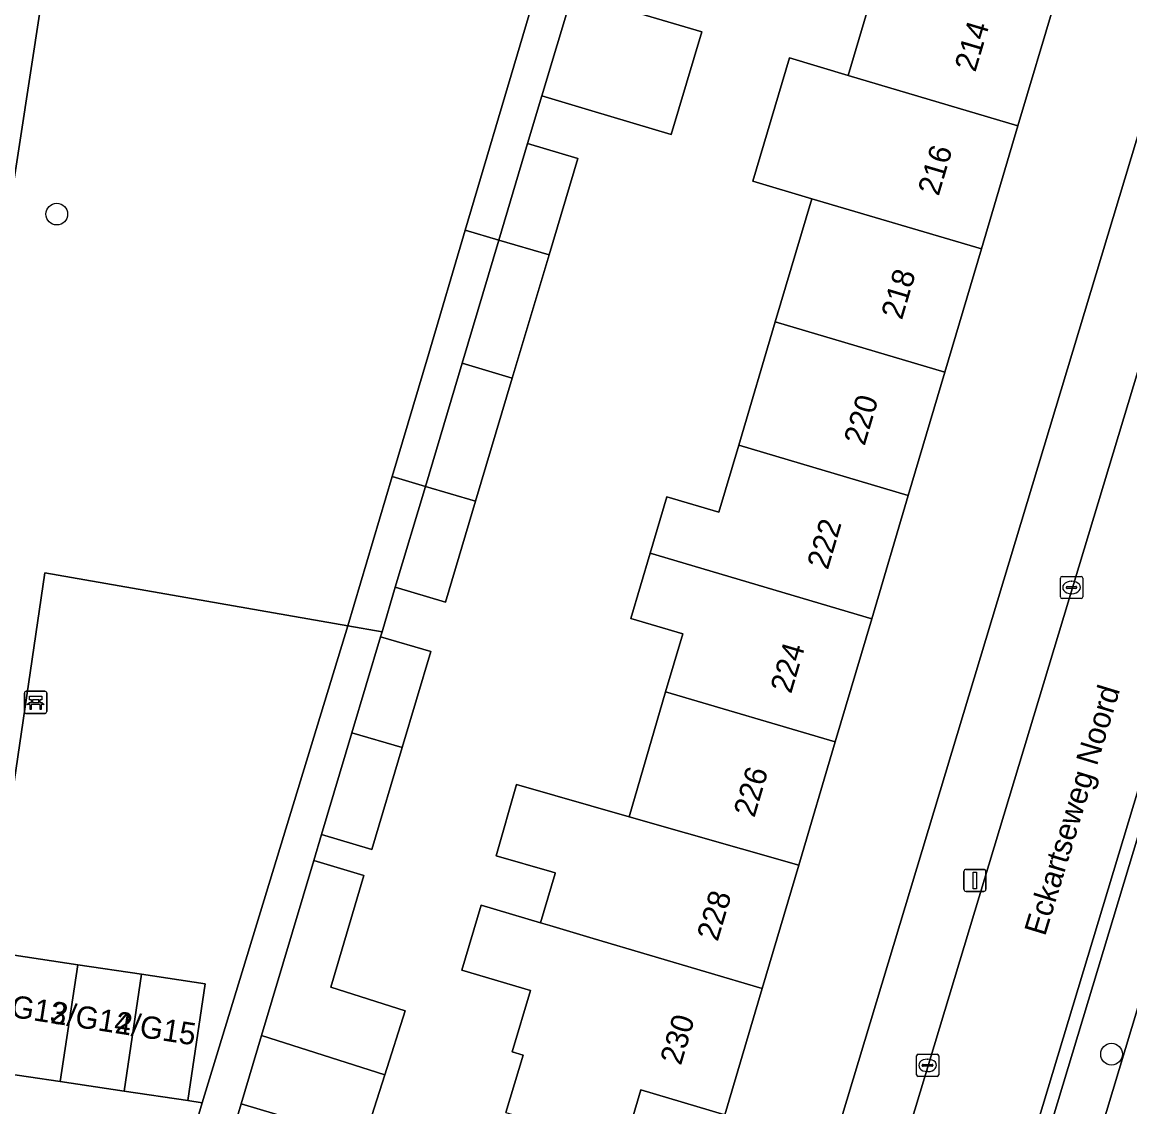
# Model space of a CAD drawing. Extents: x 161084 to 161928, y 385354 to 386522.
# Drawn here: x 161777.84 to 161827.82, y 385556.13 to 385605.07 of the extents above; entities that cross this region are included whole.
import ezdxf

# ---------------------------------------------------------------- set-up
doc = ezdxf.new("R2010")
doc.units = 0
for name, color, linetype in [('IMGEO_Bank', 7, 'Continuous'), ('IMGEO_Berm_groen', 7, 'Continuous'), ('IMGEO_Boom', 7, 'Continuous'), ('IMGEO_Erf', 7, 'Continuous'), ('IMGEO_Groenvoorziening', 7, 'Continuous'), ('IMGEO_Haag', 7, 'Continuous'), ('IMGEO_Kolk', 7, 'Continuous'), ('IMGEO_Lichtmast', 7, 'Continuous'), ('IMGEO_Openbare_ruimte_label', 7, 'Continuous'), ('IMGEO_Pand', 7, 'Continuous'), ('IMGEO_Pand_nummerreeks', 7, 'Continuous'), ('IMGEO_Rijbaan_lokaal_open', 7, 'Continuous'), ('IMGEO_Voetpad_halfverhard', 7, 'Continuous'), ('IMGEO_Voetpad_open', 7, 'Continuous')]:
    doc.layers.add(name, color=color, linetype=linetype)

msp = doc.modelspace()

# ---------------------------------------------------------------- linework, layer by layer
at = {"layer": 'IMGEO_Bank'}
for p, q in [((161777.952, 385573.949), (161777.952, 385574.79)), ((161777.952, 385574.79), (161777.952, 385573.949)), ((161778.027, 385574.874), (161778.868, 385574.874)), ((161778.868, 385574.874), (161778.027, 385574.874)), ((161778.952, 385574.799), (161778.952, 385573.958)), ((161778.952, 385573.958), (161778.952, 385574.799)), ((161778.649, 385574.272), (161778.256, 385574.272)), ((161778.261, 385574.38), (161778.261, 385574.486)), ((161778.305, 385574.486), (161778.305, 385574.38)), ((161778.593, 385574.492), (161778.311, 385574.492)), ((161778.311, 385574.374), (161778.593, 385574.374)), ((161778.599, 385574.38), (161778.599, 385574.486)), ((161778.643, 385574.486), (161778.643, 385574.38)), ((161778.877, 385573.874), (161778.036, 385573.874)), ((161778.036, 385573.874), (161778.877, 385573.874))]:
    msp.add_line(p, q, dxfattribs=at)
for points in [[(161778.255, 385574.492), (161778.169, 385574.492), (161778.169, 385574.653), (161778.732, 385574.653), (161778.732, 385574.492), (161778.649, 385574.492)], [(161778.199, 385574.272), (161778.057, 385574.272), (161778.169, 385574.374), (161778.255, 385574.374)], [(161778.249, 385574.265), (161778.249, 385574.058), (161778.206, 385574.058), (161778.206, 385574.265)], [(161778.649, 385574.374), (161778.732, 385574.374), (161778.844, 385574.272), (161778.705, 385574.272)], [(161778.699, 385574.265), (161778.699, 385574.058), (161778.655, 385574.058), (161778.655, 385574.265)]]:
    msp.add_lwpolyline(points, dxfattribs=at)
for centre, radius, start, end in [((161778.03, 385574.796), 0.0779, 92.4484, 184.2845), ((161778.03, 385574.796), 0.0779, 92.4484, 184.2845), ((161778.874, 385574.796), 0.0779, 2.4484, 94.2845), ((161778.874, 385574.796), 0.0779, 2.4484, 94.2845), ((161778.199, 385574.265), 0.00671, 2.8957, 87.1043), ((161778.256, 385574.265), 0.00671, 92.8957, 177.1043), ((161778.254, 385574.485), 0.00671, 2.8957, 87.1043), ((161778.254, 385574.381), 0.00671, 272.8957, 357.1043), ((161778.311, 385574.485), 0.00671, 92.8957, 177.1043), ((161778.311, 385574.381), 0.00671, 182.8957, 267.1043), ((161778.593, 385574.485), 0.00671, 2.8957, 87.1043), ((161778.593, 385574.381), 0.00671, 272.8957, 357.1043), ((161778.65, 385574.485), 0.00671, 92.8957, 177.1043), ((161778.65, 385574.381), 0.00671, 182.8957, 267.1043), ((161778.648, 385574.265), 0.00671, 2.8957, 87.1043), ((161778.705, 385574.265), 0.00671, 92.8957, 177.1043), ((161778.03, 385573.952), 0.0779, 182.4484, 274.2845), ((161778.03, 385573.952), 0.0779, 182.4484, 274.2845), ((161778.874, 385573.952), 0.0779, 272.4484, 4.2845), ((161778.874, 385573.952), 0.0779, 272.4484, 4.2845)]:
    msp.add_arc(centre, radius, start, end, dxfattribs=at)
at = {"layer": 'IMGEO_Berm_groen'}
msp.add_lwpolyline([(161848.199, 385627.039), (161851.849, 385628.792), (161852.899, 385629.296), (161853.927, 385643.629), (161854.018, 385644.839), (161854.228, 385647.835), (161853.097, 385647.902), (161852.678, 385647.929), (161852.218, 385647.959), (161811.076, 385511.69), (161810.035, 385508.189), (161812.346, 385507.5), (161813.227, 385511.04)], close=True, dxfattribs=at)
msp.add_lwpolyline([(161852.448, 385624.348), (161852.899, 385629.296), (161851.849, 385628.792), (161848.199, 385627.039), (161813.227, 385511.04), (161812.346, 385507.5), (161811.521, 385504.432), (161798.811, 385461.495)], dxfattribs=at)
at = {"layer": 'IMGEO_Boom'}
for centre in [(161779.407, 385596.404), (161826.988, 385558.503)]:
    msp.add_circle(centre, 0.489, dxfattribs=at)
at = {"layer": 'IMGEO_Erf'}
for points in [[(161806.19, 385527.074), (161837.789, 385631.811)], [(161799.67, 385555.866), (161800.441, 385558.464), (161799.955, 385558.608), (161800.773, 385561.368), (161797.679, 385562.286), (161798.551, 385565.225), (161801.227, 385564.432), (161801.884, 385566.652), (161801.897, 385566.683), (161801.741, 385566.728), (161799.222, 385567.448), (161800.141, 385570.667), (161805.225, 385569.215), (161806.874, 385574.857), (161807.649, 385577.474), (161805.308, 385578.167), (161806.181, 385581.113), (161806.932, 385583.649), (161809.272, 385582.955), (161810.168, 385585.979), (161811.815, 385591.541), (161813.463, 385597.102), (161810.808, 385597.889), (161812.457, 385603.451), (161815.11, 385602.664), (161816.798, 385608.363)], [(161824.455, 385606.093), (161822.766, 385600.394), (161821.118, 385594.833), (161819.469, 385589.272), (161817.821, 385583.711), (161816.173, 385578.151), (161814.525, 385572.589), (161812.877, 385567.029), (161811.228, 385561.467), (161809.539, 385555.768), (161805.752, 385556.89), (161804.982, 385554.292)], [(161804.93, 385605.688), (161808.503, 385604.623), (161807.125, 385599.997), (161803.551, 385601.062), (161801.289, 385601.736), (161800.649, 385599.59), (161802.911, 385598.916), (161801.614, 385594.565), (161799.956, 385589.006), (161798.299, 385583.451), (161796.941, 385578.897), (161794.679, 385579.571), (161794.08, 385577.564), (161794.012, 385577.338), (161796.275, 385576.664), (161794.984, 385572.333), (161793.615, 385567.742), (161791.352, 385568.416), (161791.001, 385567.238), (161793.263, 385566.564), (161791.762, 385561.529), (161795.123, 385560.462), (161794.208, 385557.577), (161793.265, 385554.605)], [(161789.989, 385555.581), (161787.726, 385556.255), (161786.961, 385553.688)]]:
    msp.add_lwpolyline(points, dxfattribs=at)
at = {"layer": 'IMGEO_Groenvoorziening'}
msp.add_lwpolyline([(161811.521, 385504.432), (161812.346, 385507.5), (161810.035, 385508.189), (161811.076, 385511.69), (161852.218, 385647.959), (161852.678, 385647.929), (161853, 385652.919), (161852.521, 385652.947), (161852.532, 385652.512), (161852.5, 385651.785), (161852.402, 385651.064), (161852.24, 385650.354), (161851.598, 385647.999), (161851.567, 385647.886), (161810.502, 385511.864), (161809.488, 385508.506), (161809.278, 385507.807), (161811.662, 385507.009), (161811.373, 385506.043), (161797.7, 385460.383), (161796.639, 385454.675), (161796.524, 385453.656), (161794.038, 385453.594)], dxfattribs=at)
msp.add_lwpolyline([(161805.27, 385620.775), (161789.899, 385624.833), (161790.31, 385626.472), (161786.741, 385626.995), (161782.033, 385627.684), (161773.386, 385571.42), (161773.877, 385571.344), (161777.482, 385570.79), (161778.873, 385580.217), (161792.543, 385577.832), (161794.539, 385584.566), (161796.185, 385590.122), (161797.834, 385595.686)], close=True, dxfattribs=at)
at = {"layer": 'IMGEO_Haag'}
msp.add_lwpolyline([(161811.521, 385504.432), (161812.346, 385507.5), (161810.035, 385508.189), (161811.076, 385511.69), (161852.218, 385647.959), (161852.678, 385647.929), (161853, 385652.919), (161852.521, 385652.947), (161852.532, 385652.512), (161852.5, 385651.785), (161852.402, 385651.064), (161852.24, 385650.354), (161851.598, 385647.999), (161851.567, 385647.886), (161810.502, 385511.864), (161809.488, 385508.506), (161809.278, 385507.807), (161811.662, 385507.009), (161811.373, 385506.043), (161797.7, 385460.383), (161796.639, 385454.675), (161796.524, 385453.656), (161794.038, 385453.594)], dxfattribs=at)
at = {"layer": 'IMGEO_Kolk'}
for p, q in [((161824.686, 385579.133), (161824.686, 385579.985)), ((161824.761, 385580.059), (161825.613, 385580.059)), ((161824.988, 385579.602), (161825.386, 385579.602)), ((161825.174, 385579.839), (161825.199, 385579.839)), ((161825.687, 385579.985), (161825.687, 385579.133)), ((161824.945, 385579.553), (161824.945, 385579.565)), ((161825.383, 385579.516), (161824.985, 385579.516)), ((161825.197, 385579.279), (161825.172, 385579.279)), ((161825.429, 385579.565), (161825.429, 385579.553)), ((161825.613, 385579.059), (161824.761, 385579.059)), ((161818.191, 385557.572), (161818.191, 385558.424)), ((161818.266, 385558.498), (161819.118, 385558.498)), ((161818.679, 385558.278), (161818.704, 385558.278)), ((161819.192, 385558.424), (161819.192, 385557.572)), ((161818.45, 385557.992), (161818.45, 385558.004)), ((161818.888, 385557.955), (161818.49, 385557.955)), ((161818.493, 385558.041), (161818.891, 385558.041)), ((161818.702, 385557.718), (161818.677, 385557.718)), ((161818.934, 385558.004), (161818.934, 385557.992)), ((161819.118, 385557.498), (161818.266, 385557.498))]:
    msp.add_line(p, q, dxfattribs=at)
for points in [[(161824.686, 385579.133), (161824.686, 385579.985)], [(161824.761, 385580.059), (161825.613, 385580.059)], [(161825.687, 385579.985), (161825.687, 385579.133)], [(161825.613, 385579.059), (161824.761, 385579.059)], [(161818.191, 385557.572), (161818.191, 385558.424)], [(161818.266, 385558.498), (161819.118, 385558.498)], [(161819.192, 385558.424), (161819.192, 385557.572)], [(161819.118, 385557.498), (161818.266, 385557.498)]]:
    msp.add_lwpolyline(points, dxfattribs=at)
for centre, radius, start, end in [((161824.763, 385579.983), 0.0765, 91.552, 178.448), ((161824.763, 385579.983), 0.0765, 91.552, 178.448), ((161824.985, 385579.562), 0.0403, 85.8775, 175.7526), ((161825.39, 385579.564), 0.0386, 1.7309, 96.639), ((161825.611, 385579.983), 0.0765, 1.552, 88.448), ((161825.611, 385579.983), 0.0765, 1.552, 88.448), ((161824.763, 385579.135), 0.0765, 181.552, 268.448), ((161824.763, 385579.135), 0.0765, 181.552, 268.448), ((161824.982, 385579.552), 0.0366, 178.938, 274.7102), ((161825.386, 385579.559), 0.043, 264.8664, 352.4533), ((161825.611, 385579.135), 0.0765, 271.552, 358.448), ((161825.611, 385579.135), 0.0765, 271.552, 358.448), ((161818.268, 385558.422), 0.0765, 91.552, 178.448), ((161818.268, 385558.422), 0.0765, 91.552, 178.448), ((161819.116, 385558.422), 0.0765, 1.552, 88.448), ((161819.116, 385558.422), 0.0765, 1.552, 88.448), ((161818.49, 385558.001), 0.0403, 85.8775, 175.7526), ((161818.487, 385557.991), 0.0366, 178.938, 274.7102), ((161818.891, 385557.998), 0.043, 264.8664, 352.4533), ((161818.895, 385558.003), 0.0386, 1.7309, 96.639), ((161818.268, 385557.574), 0.0765, 181.552, 268.448), ((161818.268, 385557.574), 0.0765, 181.552, 268.448), ((161819.116, 385557.574), 0.0765, 271.552, 358.448), ((161819.116, 385557.574), 0.0765, 271.552, 358.448)]:
    msp.add_arc(centre, radius, start, end, dxfattribs=at)
for centre, major_axis, ratio, start_param, end_param in [((161825.173, 385579.559), (-0.387, 0.002), 0.722429, 4.712389, 7.853982), ((161825.198, 385579.559), (-0.39, 0.002), 0.717154, 1.570796, 4.712389), ((161818.678, 385557.998), (-0.387, 0.002), 0.722429, 4.712389, 7.853982), ((161818.703, 385557.998), (-0.39, 0.002), 0.717154, 1.570796, 4.712389)]:
    msp.add_ellipse(centre, major_axis=major_axis, ratio=ratio, start_param=start_param, end_param=end_param, dxfattribs=at)
at = {"layer": 'IMGEO_Lichtmast'}
for p, q in [((161820.331, 385565.942), (161820.331, 385566.742)), ((161820.331, 385566.742), (161820.331, 385565.942)), ((161820.431, 385566.842), (161821.221, 385566.842)), ((161821.221, 385566.842), (161820.431, 385566.842)), ((161821.321, 385566.742), (161821.321, 385565.942)), ((161821.321, 385565.942), (161821.321, 385566.742)), ((161821.221, 385565.842), (161820.431, 385565.842)), ((161820.431, 385565.842), (161821.221, 385565.842))]:
    msp.add_line(p, q, dxfattribs=at)
msp.add_lwpolyline([(161820.751, 385566.717), (161820.901, 385566.717), (161820.901, 385565.967), (161820.751, 385565.967), (161820.751, 385566.717)], dxfattribs=at)
for centre, start, end in [((161820.431, 385566.742), 90, 180), ((161820.431, 385566.742), 90, 180), ((161821.221, 385566.742), 0, 90), ((161821.221, 385566.742), 360, 90), ((161820.431, 385565.942), 180, 270), ((161820.431, 385565.942), 180, 270), ((161821.221, 385565.942), 270, 0), ((161821.221, 385565.942), 270, 0)]:
    msp.add_arc(centre, 0.1, start, end, dxfattribs=at)
at = {"layer": 'IMGEO_Pand'}
for points in [[(161819.662, 385607.514), (161816.798, 385608.363), (161815.11, 385602.664), (161822.766, 385600.394), (161824.455, 385606.093), (161823.765, 385606.298)], [(161802.666, 385606.354), (161801.289, 385601.736), (161803.551, 385601.062), (161807.125, 385599.997), (161808.503, 385604.623), (161804.93, 385605.688)], [(161822.766, 385600.394), (161815.11, 385602.664), (161812.457, 385603.451), (161810.808, 385597.889), (161813.463, 385597.102), (161821.118, 385594.833)], [(161801.614, 385594.565), (161802.911, 385598.916), (161800.649, 385599.59), (161799.351, 385595.236)], [(161819.469, 385589.272), (161821.118, 385594.833), (161813.463, 385597.102), (161811.815, 385591.541)], [(161799.956, 385589.006), (161801.614, 385594.565), (161799.351, 385595.236), (161797.693, 385589.676)], [(161811.815, 385591.541), (161810.168, 385585.979), (161817.821, 385583.711), (161819.469, 385589.272)], [(161798.299, 385583.451), (161799.956, 385589.006), (161797.693, 385589.676), (161796.036, 385584.122)], [(161809.272, 385582.955), (161806.932, 385583.649), (161806.181, 385581.113), (161816.173, 385578.151), (161817.821, 385583.711), (161810.168, 385585.979)], [(161796.036, 385584.122), (161794.679, 385579.571), (161796.941, 385578.897), (161798.299, 385583.451)], [(161806.874, 385574.857), (161814.525, 385572.589), (161816.173, 385578.151), (161806.181, 385581.113), (161805.308, 385578.167), (161807.649, 385577.474)], [(161794.984, 385572.333), (161796.275, 385576.664), (161794.012, 385577.338), (161792.72, 385573.004)], [(161805.225, 385569.215), (161812.877, 385567.029), (161814.525, 385572.589), (161806.874, 385574.857)], [(161792.72, 385573.004), (161791.352, 385568.416), (161793.615, 385567.742), (161794.984, 385572.333)], [(161812.877, 385567.029), (161805.225, 385569.215), (161800.141, 385570.667), (161799.222, 385567.448), (161801.741, 385566.728), (161801.897, 385566.683), (161801.884, 385566.652), (161801.227, 385564.432), (161801.645, 385564.308), (161803.6, 385563.728), (161811.228, 385561.467)], [(161794.208, 385557.577), (161795.123, 385560.462), (161791.762, 385561.529), (161793.263, 385566.564), (161791.001, 385567.238), (161788.646, 385559.341)], [(161811.228, 385561.467), (161803.6, 385563.728), (161801.645, 385564.308), (161801.227, 385564.432), (161798.551, 385565.225), (161797.679, 385562.286), (161800.773, 385561.368), (161799.955, 385558.608), (161800.441, 385558.464), (161799.67, 385555.866), (161804.982, 385554.292), (161805.752, 385556.89), (161809.539, 385555.768)], [(161779.566, 385557.266), (161780.356, 385562.539), (161777.481, 385562.97), (161776.691, 385557.696)], [(161782.44, 385556.835), (161783.23, 385562.109), (161780.356, 385562.539), (161779.566, 385557.266)], [(161785.315, 385556.405), (161786.105, 385561.678), (161783.23, 385562.109), (161782.44, 385556.835)], [(161788.646, 385559.341), (161787.726, 385556.255), (161789.989, 385555.581), (161793.265, 385554.605), (161794.208, 385557.577)]]:
    msp.add_lwpolyline(points, close=True, dxfattribs=at)
at = {"layer": 'IMGEO_Rijbaan_lokaal_open'}
for points in [[(161851.567, 385647.886), (161851.598, 385647.999), (161846.433, 385649.859), (161834.105, 385608.968), (161832.229, 385602.755), (161817.434, 385553.757), (161815.651, 385547.851), (161808.581, 385524.436), (161808.494, 385524.175), (161803.895, 385509.219), (161801.247, 385500), (161800.149, 385496.305), (161790.091, 385463.059), (161789.139, 385458.96), (161788.558, 385454.793), (161788.351, 385450.59), (161788.44, 385447.473), (161789.704, 385438.084), (161790.324, 385434.924), (161795.608, 385436.175), (161794.783, 385440.788)], [(161794.175, 385455.066), (161794.324, 385456.287), (161796.052, 385463.546), (161806.92, 385500), (161808.984, 385506.835), (161809.278, 385507.807), (161809.488, 385508.506), (161810.502, 385511.864), (161851.567, 385647.886)]]:
    msp.add_lwpolyline(points, dxfattribs=at)
msp.add_lwpolyline([(161785.315, 385556.405), (161782.44, 385556.835), (161779.566, 385557.266), (161776.691, 385557.696), (161776.463, 385556.324), (161776.038, 385553.531), (161775.613, 385550.738), (161775.188, 385547.945), (161774.763, 385545.152), (161774.34, 385542.372), (161773.525, 385537.018), (161770.76, 385537.439), (161767.996, 385537.859), (161765.231, 385538.28), (161762.467, 385538.7), (161759.702, 385539.121), (161756.938, 385539.541), (161754.173, 385539.962), (161778.928, 385532.31), (161785.968, 385556.308)], close=True, dxfattribs=at)
at = {"layer": 'IMGEO_Voetpad_halfverhard'}
msp.add_lwpolyline([(161796.036, 385584.122), (161794.539, 385584.566), (161792.543, 385577.832), (161794.08, 385577.564), (161794.679, 385579.571)], close=True, dxfattribs=at)
at = {"layer": 'IMGEO_Voetpad_open'}
for points in [[(161801.289, 385601.736), (161802.666, 385606.354), (161805.019, 385614.244), (161805.864, 385617.079), (161807.502, 385622.57), (161807.716, 385623.288), (161809.178, 385628.191), (161810.745, 385633.446), (161811.048, 385634.401), (161812.394, 385638.915), (161810.788, 385639.393), (161805.726, 385622.313), (161805.27, 385620.775), (161797.834, 385595.686), (161799.351, 385595.236), (161800.649, 385599.59)], [(161782.033, 385627.684), (161779.887, 385627.999), (161779.086, 385622.106), (161778.471, 385618.075), (161777.843, 385613.902), (161777.287, 385610.242), (161776.737, 385606.625), (161776.119, 385602.562), (161775.499, 385598.484), (161774.881, 385594.416), (161774.32, 385590.728), (161773.696, 385586.62), (161773.07, 385582.502), (161772.508, 385578.805), (161771.867, 385574.591), (161771.416, 385571.723), (161773.386, 385571.42)], [(161799.351, 385595.236), (161797.834, 385595.686), (161796.185, 385590.122), (161794.539, 385584.566), (161796.036, 385584.122), (161797.693, 385589.676)], [(161792.543, 385577.832), (161778.873, 385580.217), (161777.482, 385570.79), (161773.877, 385571.344), (161773.386, 385571.42), (161771.19, 385557.126), (161771.52, 385557.076), (161776.463, 385556.324), (161776.691, 385557.696), (161777.481, 385562.97), (161780.356, 385562.539), (161783.23, 385562.109), (161786.105, 385561.678), (161785.315, 385556.405), (161785.968, 385556.308)], [(161787.726, 385556.255), (161788.646, 385559.341), (161791.001, 385567.238), (161791.352, 385568.416), (161792.72, 385573.004), (161794.012, 385577.338), (161794.08, 385577.564), (161792.543, 385577.832), (161785.968, 385556.308), (161778.928, 385532.31), (161780.461, 385531.837), (161782.887, 385540.031), (161783.145, 385540.894), (161784.588, 385545.731), (161785.198, 385547.778), (161786.228, 385551.232), (161786.961, 385553.688)]]:
    msp.add_lwpolyline(points, close=True, dxfattribs=at)
for points in [[(161837.789, 385631.811), (161806.19, 385527.074)], [(161817.434, 385553.757), (161832.229, 385602.755), (161831.698, 385602.915), (161833.568, 385609.13)]]:
    msp.add_lwpolyline(points, dxfattribs=at)

# ---------------------------------------------------------------- texts
at = {"layer": 'IMGEO_Openbare_ruimte_label'}
msp.add_text('Eckartseweg Noord', height=1, rotation=73.0868, dxfattribs=at).set_placement((161823.99, 385563.794))
at = {"layer": 'IMGEO_Pand_nummerreeks'}
for s, rotation, p in [('214', 73.4905, (161820.845, 385602.779)), ('216', 73.4933, (161819.188, 385597.189)), ('218', 73.4905, (161817.531, 385591.599)), ('220', 73.4905, (161815.848, 385585.919)), ('222', 73.4905, (161814.189, 385580.322)), ('224', 73.4905, (161812.532, 385574.733)), ('226', 73.4905, (161810.875, 385569.141)), ('228', 73.4933, (161809.219, 385563.554)), ('2/G13', 351.142, (161776.184, 385560.364)), ('2/G14', 351.142, (161779.09, 385559.911)), ('2/G15', 351.142, (161781.996, 385559.458)), ('230', 73.4933, (161807.561, 385557.962))]:
    msp.add_text(s, height=1, rotation=rotation, dxfattribs=at).set_placement(p)

doc.saveas('drawing.dxf')
